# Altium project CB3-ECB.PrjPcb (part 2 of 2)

## Sheet BBoard-JX2.SchDoc: Eval Board -  BBoard JX1 connector (PWM, GPIO)
size A3; ApprovedBy: Nicolas Cherix; Author: O. Guinnard; Organization: imperix Ltd; Address1: Rue de l'Industrie 10; Address2: 1950 Sion; Address3: Switzerland; Address4: +41 27 552 06 60; Revision: C1; SheetNumber: 5; SheetTotal: 6
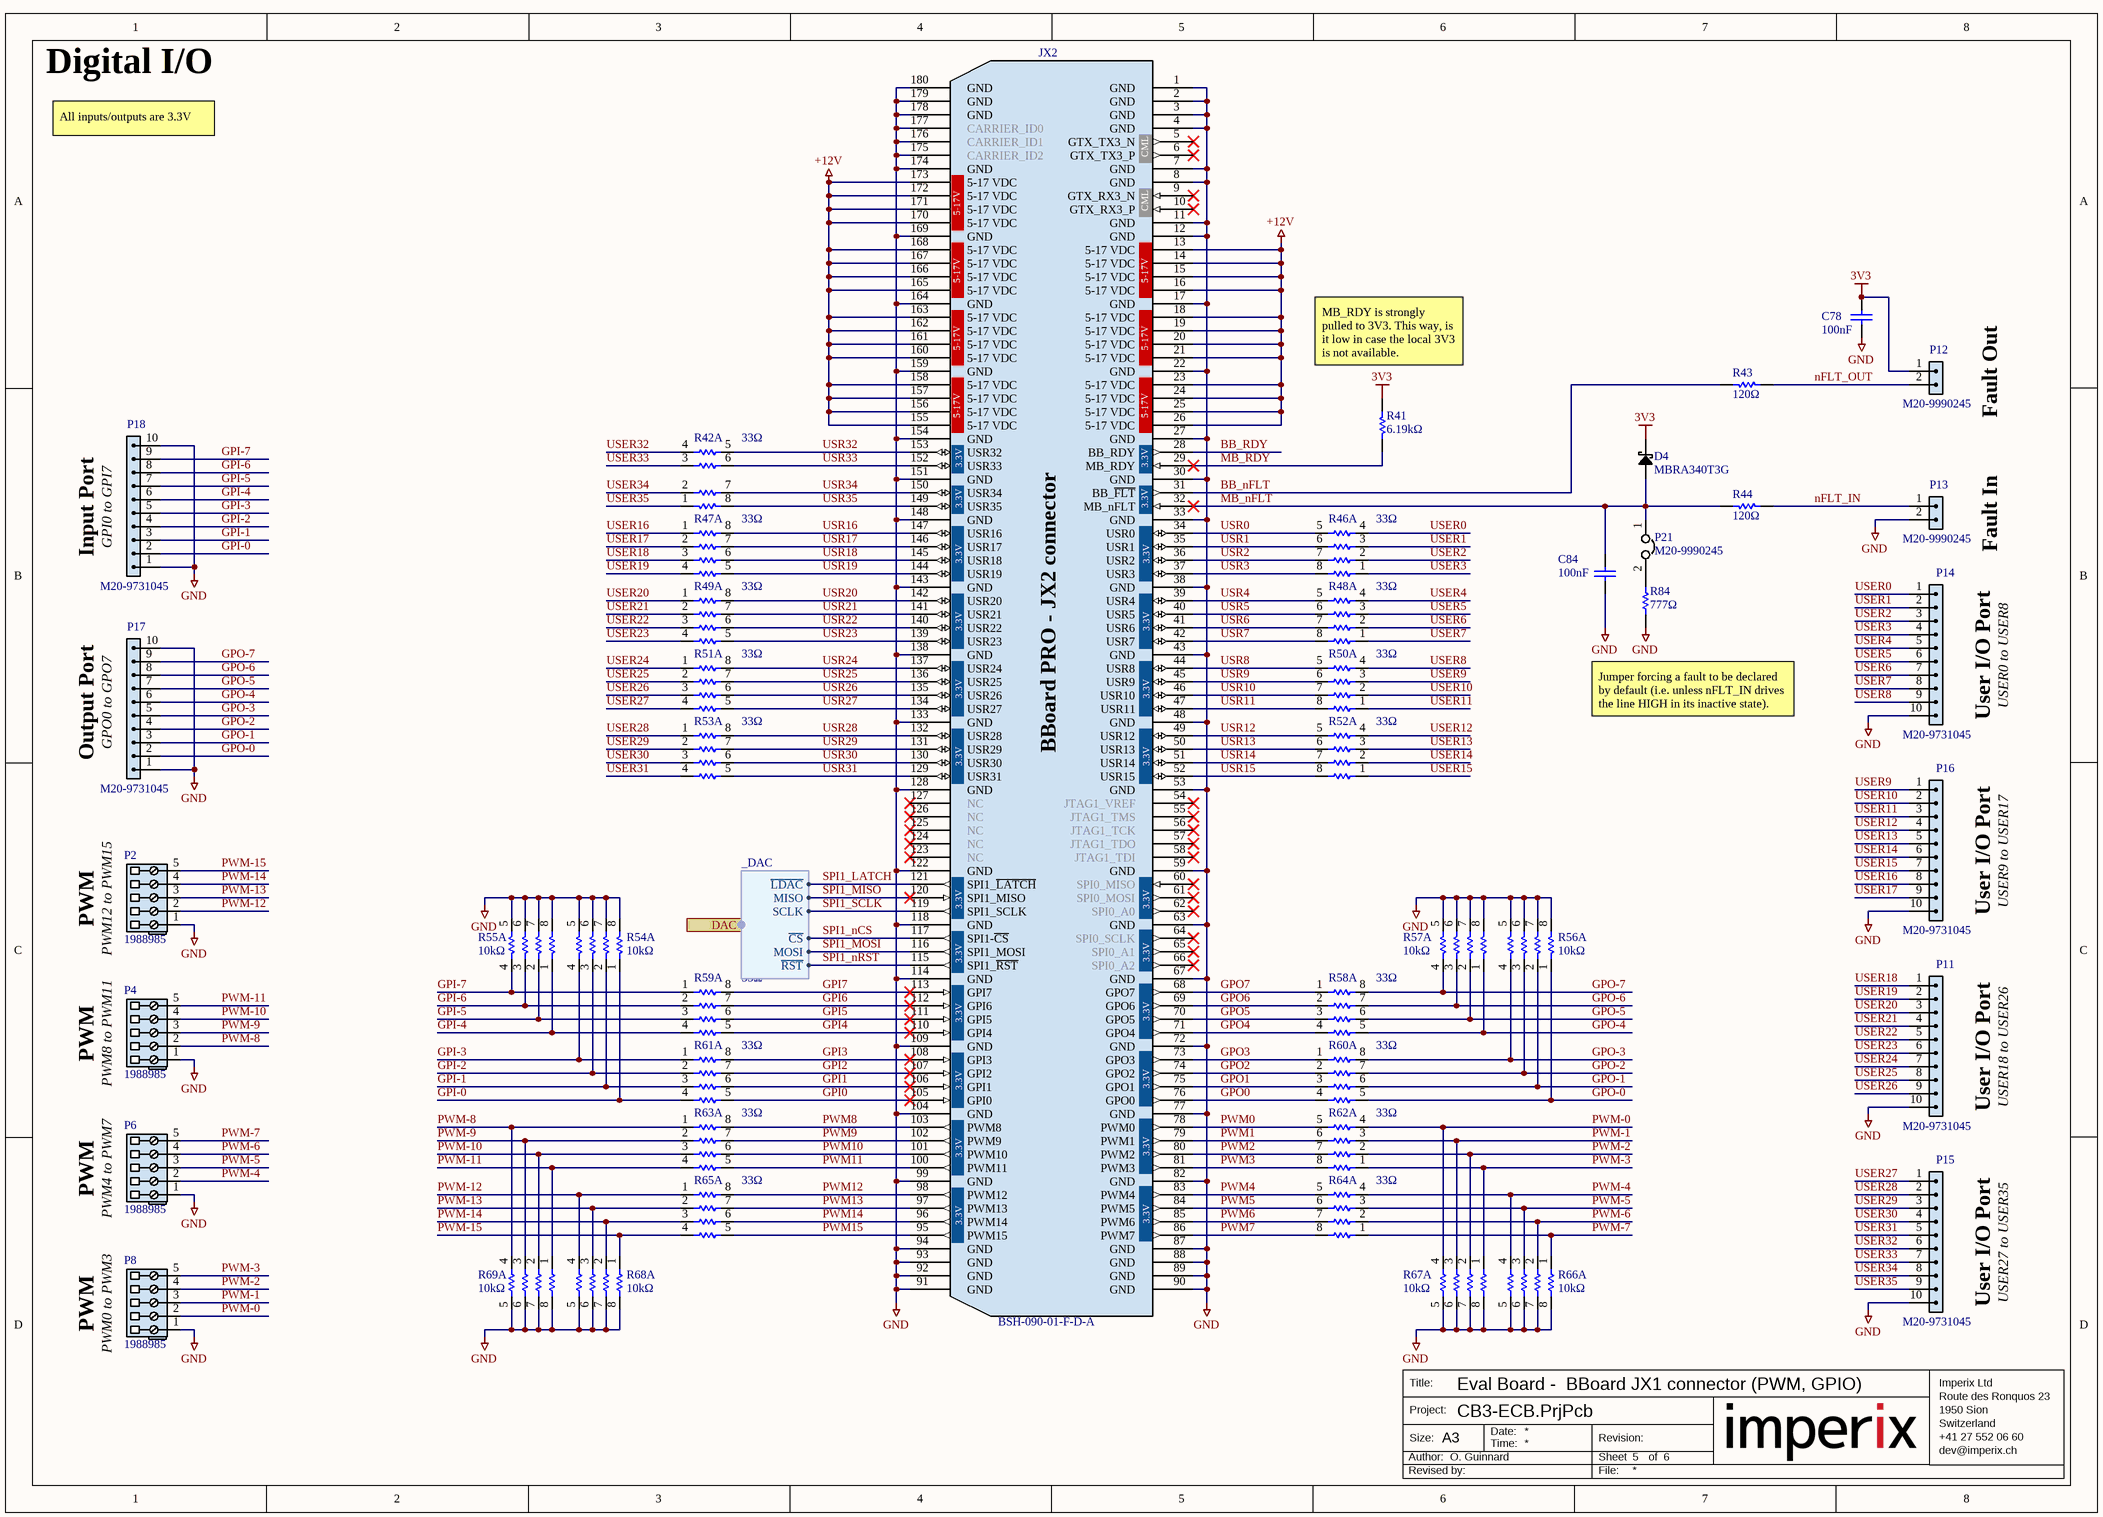
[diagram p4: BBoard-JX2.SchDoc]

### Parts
C78  value 100nF  [CAPC1005L(0402)]  (hidden comment: CAP-100NF-25V-X7R-0402-10%)
C84  value 100nF  [CAPC1005L(0402)]  (hidden comment: CAP-100NF-25V-X7R-0402-10%)
D4  MBRA340T3G  [DO-214AC]
JX2  BSH-090-01-F-D-A  [BSH-090-01-F-D-A]
P2  1988985  [1988985]
P4  1988985  [1988985]
P6  1988985  [1988985]
P8  1988985  [1988985]
P11  M20-9731045  [M20-9731045]
P12  M20-9990245  [M20-9990245]
P13  M20-9990245  [M20-9990245]
P14  M20-9731045  [M20-9731045]
P15  M20-9731045  [M20-9731045]
P16  M20-9731045  [M20-9731045]
P17  M20-9731045  [M20-9731045]
P18  M20-9731045  [M20-9731045]
P21  M20-9990245  [M20-9990245]
R41  value 6.19kΩ  [RESC1005L(0402)]  (hidden comment: RES-6.19KΩ-1/16W-100PPM-0402-1%)
R42  value 33Ω  [RESQUAD0804]  (hidden comment: EXB-28V330JX)  (parts A,B,C,D of 4)
R43  value 120Ω  [RESC1005L(0402)]  (hidden comment: RES-120Ω-1/16W-25PPM-0402-0.1%)
R44  value 120Ω  [RESC1005L(0402)]  (hidden comment: RES-120Ω-1/16W-25PPM-0402-0.1%)
R46  value 33Ω  [RESQUAD0804]  (hidden comment: EXB-28V330JX)  (parts A,B,C,D of 4)
R47  value 33Ω  [RESQUAD0804]  (hidden comment: EXB-28V330JX)  (parts A,B,C,D of 4)
R48  value 33Ω  [RESQUAD0804]  (hidden comment: EXB-28V330JX)  (parts A,B,C,D of 4)
R49  value 33Ω  [RESQUAD0804]  (hidden comment: EXB-28V330JX)  (parts A,B,C,D of 4)
R50  value 33Ω  [RESQUAD0804]  (hidden comment: EXB-28V330JX)  (parts A,B,C,D of 4)
R51  value 33Ω  [RESQUAD0804]  (hidden comment: EXB-28V330JX)  (parts A,B,C,D of 4)
R52  value 33Ω  [RESQUAD0804]  (hidden comment: EXB-28V330JX)  (parts A,B,C,D of 4)
R53  value 33Ω  [RESQUAD0804]  (hidden comment: EXB-28V330JX)  (parts A,B,C,D of 4)
R54  value 10kΩ  [RESQUAD0804]  (hidden comment: EXB-28V103JX)  (parts A,B,C,D of 4)
R55  value 10kΩ  [RESQUAD0804]  (hidden comment: EXB-28V103JX)  (parts A,B,C,D of 4)
R56  value 10kΩ  [RESQUAD0804]  (hidden comment: EXB-28V103JX)  (parts A,B,C,D of 4)
R57  value 10kΩ  [RESQUAD0804]  (hidden comment: EXB-28V103JX)  (parts A,B,C,D of 4)
R58  value 33Ω  [RESQUAD0804]  (hidden comment: EXB-28V330JX)  (parts A,B,C,D of 4)
R59  value 33Ω  [RESQUAD0804]  (hidden comment: EXB-28V330JX)  (parts A,B,C,D of 4)
R60  value 33Ω  [RESQUAD0804]  (hidden comment: EXB-28V330JX)  (parts A,B,C,D of 4)
R61  value 33Ω  [RESQUAD0804]  (hidden comment: EXB-28V330JX)  (parts A,B,C,D of 4)
R62  value 33Ω  [RESQUAD0804]  (hidden comment: EXB-28V330JX)  (parts A,B,C,D of 4)
R63  value 33Ω  [RESQUAD0804]  (hidden comment: EXB-28V330JX)  (parts A,B,C,D of 4)
R64  value 33Ω  [RESQUAD0804]  (hidden comment: EXB-28V330JX)  (parts A,B,C,D of 4)
R65  value 33Ω  [RESQUAD0804]  (hidden comment: EXB-28V330JX)  (parts A,B,C,D of 4)
R66  value 10kΩ  [RESQUAD0804]  (hidden comment: EXB-28V103JX)  (parts A,B,C,D of 4)
R67  value 10kΩ  [RESQUAD0804]  (hidden comment: EXB-28V103JX)  (parts A,B,C,D of 4)
R68  value 10kΩ  [RESQUAD0804]  (hidden comment: EXB-28V103JX)  (parts A,B,C,D of 4)
R69  value 10kΩ  [RESQUAD0804]  (hidden comment: EXB-28V103JX)  (parts A,B,C,D of 4)
R84  value 777Ω  [RESC1005L(0402)]  (hidden comment: RES-777Ω-1/16W-25PPM-0402-0.1%)

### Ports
DAC (harness _DAC)

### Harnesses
_DAC: MOSI, MISO, SCLK, ~{CS}, ~{LDAC}, ~{RST}

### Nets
3V3: C78.2 D4.K P12.1 R41.1
+12V: JX2.13(5-17_VDC) JX2.14(5-17_VDC) JX2.15(5-17_VDC) JX2.16(5-17_VDC) JX2.18(5-17_VDC) JX2.19(5-17_VDC) JX2.20(5-17_VDC) JX2.21(5-17_VDC) JX2.23(5-17_VDC) JX2.24(5-17_VDC) JX2.25(5-17_VDC) JX2.26(5-17_VDC) JX2.155(5-17_VDC) JX2.156(5-17_VDC) JX2.157(5-17_VDC) JX2.158(5-17_VDC) JX2.160(5-17_VDC) JX2.161(5-17_VDC) JX2.162(5-17_VDC) JX2.163(5-17_VDC) JX2.165(5-17_VDC) JX2.166(5-17_VDC) JX2.167(5-17_VDC) JX2.168(5-17_VDC) JX2.170(5-17_VDC) JX2.171(5-17_VDC) JX2.172(5-17_VDC) JX2.173(5-17_VDC)
GND: C78.1 C84.1 JX2.1(GND) JX2.2(GND) JX2.3(GND) JX2.4(GND) JX2.7(GND) JX2.8(GND) JX2.11(GND) JX2.12(GND) JX2.17(GND) JX2.22(GND) JX2.27(GND) JX2.30(GND) JX2.33(GND) JX2.38(GND) JX2.43(GND) JX2.48(GND) JX2.53(GND) JX2.59(GND) JX2.63(GND) JX2.67(GND) JX2.72(GND) JX2.77(GND) JX2.82(GND) JX2.87(GND) JX2.88(GND) JX2.89(GND) JX2.90(GND) JX2.91(GND) JX2.92(GND) JX2.93(GND) JX2.94(GND) JX2.99(GND) JX2.104(GND) JX2.109(GND) JX2.114(GND) JX2.118(GND) JX2.122(GND) JX2.128(GND) JX2.133(GND) JX2.138(GND) JX2.143(GND) JX2.148(GND) JX2.151(GND) JX2.154(GND) JX2.159(GND) JX2.164(GND) JX2.169(GND) JX2.174(GND) JX2.175(CARRIER_ID2) JX2.176(CARRIER_ID1) JX2.177(CARRIER_ID0) JX2.178(GND) JX2.179(GND) JX2.180(GND) P2.1 P4.1 P6.1 P8.1 P11.10 P13.2 P14.10 P15.10 P16.10 P17.1 P17.10 P18.1 P18.10 R54.5 R54.6 R54.7 R54.8 R55.5 R55.6 R55.7 R55.8 R56.5 R56.6 R56.7 R56.8 R57.5 R57.6 R57.7 R57.8 R66.5 R66.6 R66.7 R66.8 R67.5 R67.6 R67.7 R67.8 R68.5 R68.6 R68.7 R68.8 R69.5 R69.6 R69.7 R69.8 R84.1
BB_nFLT: JX2.31(BB_~{FLT}) R43.1
BB_RDY: JX2.28(BB_RDY)
GPI0: JX2.105(GPI0) R61.5
GPI1: JX2.106(GPI1) R61.6
GPI2: JX2.107(GPI2) R61.7
GPI3: JX2.108(GPI3) R61.8
GPI4: JX2.110(GPI4) R59.5
GPI5: JX2.111(GPI5) R59.6
GPI6: JX2.112(GPI6) R59.7
GPI7: JX2.113(GPI7) R59.8
GPI-0: P18.2 R54.1 R61.4
GPI-1: P18.3 R54.2 R61.3
GPI-2: P18.4 R54.3 R61.2
GPI-3: P18.5 R54.4 R61.1
GPI-4: P18.6 R55.1 R59.4
GPI-5: P18.7 R55.2 R59.3
GPI-6: P18.8 R55.3 R59.2
GPI-7: P18.9 R55.4 R59.1
GPO0: JX2.76(GPO0) R60.4
GPO1: JX2.75(GPO1) R60.3
GPO2: JX2.74(GPO2) R60.2
GPO3: JX2.73(GPO3) R60.1
GPO4: JX2.71(GPO4) R58.4
GPO5: JX2.70(GPO5) R58.3
GPO6: JX2.69(GPO6) R58.2
GPO7: JX2.68(GPO7) R58.1
GPO-0: P17.2 R56.1 R60.5
GPO-1: P17.3 R56.2 R60.6
GPO-2: P17.4 R56.3 R60.7
GPO-3: P17.5 R56.4 R60.8
GPO-4: P17.6 R57.1 R58.5
GPO-5: P17.7 R57.2 R58.6
GPO-6: P17.8 R57.3 R58.7
GPO-7: P17.9 R57.4 R58.8
MB_nFLT: C84.2 D4.A JX2.32(MB_nFLT) P21.1 R44.1
MB_RDY: JX2.29(MB_RDY) R41.2
nFLT_IN: P13.1 R44.2
nFLT_OUT: P12.2 R43.2
PWM0: JX2.78(PWM0) R62.5
PWM1: JX2.79(PWM1) R62.6
PWM2: JX2.80(PWM2) R62.7
PWM3: JX2.81(PWM3) R62.8
PWM4: JX2.83(PWM4) R64.5
PWM5: JX2.84(PWM5) R64.6
PWM6: JX2.85(PWM6) R64.7
PWM7: JX2.86(PWM7) R64.8
PWM8: JX2.103(PWM8) R63.8
PWM9: JX2.102(PWM9) R63.7
PWM10: JX2.101(PWM10) R63.6
PWM11: JX2.100(PWM11) R63.5
PWM12: JX2.98(PWM12) R65.8
PWM13: JX2.97(PWM13) R65.7
PWM14: JX2.96(PWM14) R65.6
PWM15: JX2.95(PWM15) R65.5
PWM-0: P8.2 R62.4 R67.4
PWM-1: P8.3 R62.3 R67.3
PWM-2: P8.4 R62.2 R67.2
PWM-3: P8.5 R62.1 R67.1
PWM-4: P6.2 R64.4 R66.4
PWM-5: P6.3 R64.3 R66.3
PWM-6: P6.4 R64.2 R66.2
PWM-7: P6.5 R64.1 R66.1
PWM-8: P4.2 R63.1 R69.4
PWM-9: P4.3 R63.2 R69.3
PWM-10: P4.4 R63.3 R69.2
PWM-11: P4.5 R63.4 R69.1
PWM-12: P2.2 R65.1 R68.4
PWM-13: P2.3 R65.2 R68.3
PWM-14: P2.4 R65.3 R68.2
PWM-15: P2.5 R65.4 R68.1
SPI1_LATCH: JX2.121(SPI1_~{LATCH}) ; port DAC.~{LDAC}
SPI1_MISO: JX2.120(SPI1_MISO) ; port DAC.MISO
SPI1_MOSI: JX2.116(SPI1_MOSI) ; port DAC.MOSI
SPI1_nCS: JX2.117(SPI1-~{CS}) ; port DAC.~{CS}
SPI1_nRST: JX2.115(SPI1_~{RST}) ; port DAC.~{RST}
SPI1_SCLK: JX2.119(SPI1_SCLK) ; port DAC.SCLK
USER0: P14.1 R46.4
USER1: P14.2 R46.3
USER2: P14.3 R46.2
USER3: P14.4 R46.1
USER4: P14.5 R48.4
USER5: P14.6 R48.3
USER6: P14.7 R48.2
USER7: P14.8 R48.1
USER8: P14.9 R50.4
USER9: P16.1 R50.3
USER10: P16.2 R50.2
USER11: P16.3 R50.1
USER12: P16.4 R52.4
USER13: P16.5 R52.3
USER14: P16.6 R52.2
USER15: P16.7 R52.1
USER16: P16.8 R47.1
USER17: P16.9 R47.2
USER18: P11.1 R47.3
USER19: P11.2 R47.4
USER20: P11.3 R49.1
USER21: P11.4 R49.2
USER22: P11.5 R49.3
USER23: P11.6 R49.4
USER24: P11.7 R51.1
USER25: P11.8 R51.2
USER26: P11.9 R51.3
USER27: P15.1 R51.4
USER28: P15.2 R53.1
USER29: P15.3 R53.2
USER30: P15.4 R53.3
USER31: P15.5 R53.4
USER32: P15.6 R42.4
USER33: P15.7 R42.3
USER34: P15.8 R42.2
USER35: P15.9 R42.1
USR0: JX2.34(USR0) R46.5
USR1: JX2.35(USR1) R46.6
USR2: JX2.36(USR2) R46.7
USR3: JX2.37(USR3) R46.8
USR4: JX2.39(USR4) R48.5
USR5: JX2.40(USR5) R48.6
USR6: JX2.41(USR6) R48.7
USR7: JX2.42(USR7) R48.8
USR8: JX2.44(USR8) R50.5
USR9: JX2.45(USR9) R50.6
USR10: JX2.46(USR10) R50.7
USR11: JX2.47(USR11) R50.8
USR12: JX2.49(USR12) R52.5
USR13: JX2.50(USR13) R52.6
USR14: JX2.51(USR14) R52.7
USR15: JX2.52(USR15) R52.8
USR16: JX2.147(USR16) R47.8
USR17: JX2.146(USR17) R47.7
USR18: JX2.145(USR18) R47.6
USR19: JX2.144(USR19) R47.5
USR20: JX2.142(USR20) R49.8
USR21: JX2.141(USR21) R49.7
USR22: JX2.140(USR22) R49.6
USR23: JX2.139(USR23) R49.5
USR24: JX2.137(USR24) R51.8
USR25: JX2.136(USR25) R51.7
USR26: JX2.135(USR26) R51.6
USR27: JX2.134(USR27) R51.5
USR28: JX2.132(USR28) R53.8
USR29: JX2.131(USR29) R53.7
USR30: JX2.130(USR30) R53.6
USR31: JX2.129(USR31) R53.5
USR32: JX2.153(USR32) R42.5
USR33: JX2.152(USR33) R42.6
USR34: JX2.150(USR34) R42.7
USR35: JX2.149(USR35) R42.8
NetP21_2: P21.2 R84.2

Not connected (* = marked no-connect by the designer): JX2 5(GTX_TX3_N)* 6(GTX_TX3_P)* 9(GTX_RX3_N)* 10(GTX_RX3_P)* 54(JTAG1_VREF)* 55(JTAG1_TMS)* 56(JTAG1_TCK)* 57(JTAG1_TDO)* 58(JTAG1_TDI)* 60(SPI0_MISO)* 61(SPI0_MOSI)* 62(SPI0_A0)* 64(SPI0_SCLK)* 65(SPI0_A1)* 66(SPI0_A2)* 123(NC)* 124(NC)* 125(NC)* 126(NC)* 127(NC)*

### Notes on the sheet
- Digital I/O
- All inputs/outputs are 3.3V
- (near R41) MB_RDY is strongly pulled to 3V3. This way, is it low in case the local 3V3 is not available.
- (near P12) Fault Out
- (near P18) Input Port
- (near P18) GPI0 to GPI7
- Fault In
- (near P14) User I/O Port
- USER0 to USER8
- (near P17) Output Port
- (near P17) GPO0 to GPO7
- (near R84) Jumper forcing a fault to be declared by default (i.e. unless nFLT_IN drives the line HIGH in its inactive state).
- (near P16) User I/O Port
- USER9 to USER17
- PWM
- PWM12 to PWM15
- PWM8 to PWM11
- (near P11) User I/O Port
- USER18 to USER26
- (near P6) PWM4 to PWM7
- (near P15) User I/O Port
- USER27 to USER35
- (near P8) PWM0 to PWM3

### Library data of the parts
C78 C84 = CMP-004-000006-18: CAP CER 100NF 25V X7R 0402 10% (Generic Imperix Component)
D4 = CMP-005-000028-6: Diode Schottky 40 V 3A Surface Mount SMA; Max Forward Surge Current (Ifsm): 100A; Max Repetitive Reverse Voltage (Vrrm): 40V; Polarity: Standard; Element Configuration: Single; Forward Voltage: 450mV; Max Reverse Current: 300uA
JX2 = CMP-070-000034-11: JX2 for BBoard; Max Current Rating: 1.25A; Number of Positions: 180; Max Voltage Rating (AC): 125V; Gender: Female; Mated Stacking Heights: 5mm; Pitch: 0.5mm
P2 P4 P6 P8 = CMP-003-000046-13: Conn PC Terminal Block 5 POS 3.5mm Solder Thru-Hole 17.5A; Number of Poles: 5; Voltage: 300V; Current: 10A; Approvals: UL,EAC; Number of Levels: 1; Wire Gauge (Max): 26AWG; Gender: Male; Wire Gauge (Min): 16AWG; Voltage Rating: 160V
P11 P14-P18 = CMP-003-000044-17: Connector Header Through Hole 10 position 0.100" (2.54mm); Mated Stacking Heights: 16.54mm; Current Rating: 3A; Number of Positions: 10; Voltage Rating: 750V; Gender: Male
P12 P13 = CMP-003-000045-14: Connector Header Through Hole 2 position 0.100" (2.54mm); Working Voltage: 750V; Gender: Male; Number of Positions: 2; Insulation Resistance: 10GR; Contact Resistance: 25mR; Mated Stacking Heights: 16.54mm; Current Rating: 3A; Mating Cycles: 300; Voltage: 50V
P21 = CMP-070-000025-6: Connector Header Through Hole 2 position 0.100" (2.54mm); Max Current Rating: 3A; Voltage Rating (AC): 750V; Number of Contacts: 2; Contact Resistance: 25mR; Gender: Male; Insulation Resistance: 10GR; Mating Cycles: 300; Mated Stacking Heights: 16.54mm; Voltage: 50V
R41 = CMP-009-000034-6: RES SMD 6.19KΩ 1/16W 100PPM 0402 1% (Generic Imperix Component); Temperature Coefficient: 100ppm/°C
R42 R46-R53 R58-R65 = CMP-009-000035-3: Res Thick Film Array 33 Ohm 5% ±200ppm/°C ISOL 8-Pin 0804(4 X 0402) Convex SMD Automotive T/R; Power Rating: 62.5mW; Voltage Rating (DC): 100V; Circuit Type: Isolated; Power Dissipation: 63mW; Number of Elements: 4; Number of Contacts: 8; Voltage Rating: 50V
R43 R44 = CMP-017-000008-4: RES SMD 120Ω 1/16W 25PPM 0402 0.1% (Generic Imperix Component); Temperature Coefficient: 25ppm/°C
R54-R57 R66-R69 = CMP-062-000000-4: Res Thick Film Array 10KΩ 5% ±200ppm/°C ISOL 8-Pin 0804(4 X 0402) Convex SMD Automotive T/R; Circuit Type: Isolated; Number of Contacts: 8; Number of Elements: 4; Power Dissipation: 63mW; Power Per Element: 62.5mW; Voltage Rating (DC): 100V; Voltage Rating: 50V
R84 = CMP-150-000004-2: RES SMD 777Ω 1/16W 25PPM 0402 0.1% (Generic Imperix Component); Temperature Coefficient: 25ppm/°C

## Sheet Test points.SchDoc: Eval Board -  Test points
size A3; ApprovedBy: Nicolas Cherix; Author: O. Guinnard; Organization: imperix Ltd; Address1: Rue de l'Industrie 10; Address2: 1950 Sion; Address3: Switzerland; Address4: +41 27 552 06 60; Revision: C1; SheetNumber: 6; SheetTotal: 6
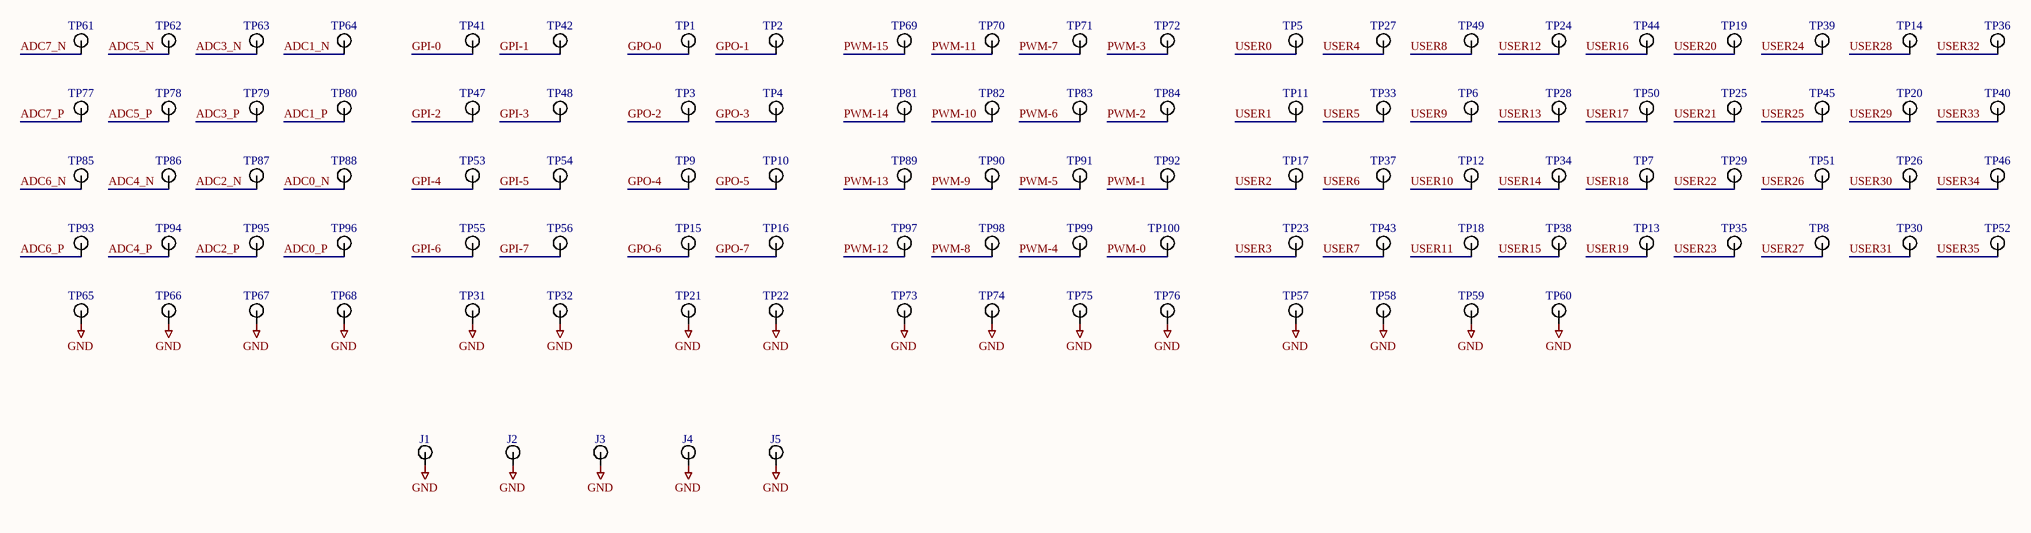
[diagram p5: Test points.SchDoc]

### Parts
J1  1625854-1  [TP-3216L(1206)]  (value not drawn)
J2  1625854-1  [TP-3216L(1206)]  (value not drawn)
J3  1625854-1  [TP-3216L(1206)]  (value not drawn)
J4  1625854-1  [TP-3216L(1206)]  (value not drawn)
J5  1625854-1  [TP-3216L(1206)]  (value not drawn)
TP1  5001  [5001]  (value not drawn)
TP2  5001  [5001]  (value not drawn)
TP3  5001  [5001]  (value not drawn)
TP4  5001  [5001]  (value not drawn)
TP5  5001  [5001]  (value not drawn)
TP6  5001  [5001]  (value not drawn)
TP7  5001  [5001]  (value not drawn)
TP8  5001  [5001]  (value not drawn)
TP9  5001  [5001]  (value not drawn)
TP10  5001  [5001]  (value not drawn)
TP11  5001  [5001]  (value not drawn)
TP12  5001  [5001]  (value not drawn)
TP13  5001  [5001]  (value not drawn)
TP14  5001  [5001]  (value not drawn)
TP15  5001  [5001]  (value not drawn)
TP16  5001  [5001]  (value not drawn)
TP17  5001  [5001]  (value not drawn)
TP18  5001  [5001]  (value not drawn)
TP19  5001  [5001]  (value not drawn)
TP20  5001  [5001]  (value not drawn)
TP21  5001  [5001]  (value not drawn)
TP22  5001  [5001]  (value not drawn)
TP23  5001  [5001]  (value not drawn)
TP24  5001  [5001]  (value not drawn)
TP25  5001  [5001]  (value not drawn)
TP26  5001  [5001]  (value not drawn)
TP27  5001  [5001]  (value not drawn)
TP28  5001  [5001]  (value not drawn)
TP29  5001  [5001]  (value not drawn)
TP30  5001  [5001]  (value not drawn)
TP31  5001  [5001]  (value not drawn)
TP32  5001  [5001]  (value not drawn)
TP33  5001  [5001]  (value not drawn)
TP34  5001  [5001]  (value not drawn)
TP35  5001  [5001]  (value not drawn)
TP36  5001  [5001]  (value not drawn)
TP37  5001  [5001]  (value not drawn)
TP38  5001  [5001]  (value not drawn)
TP39  5001  [5001]  (value not drawn)
TP40  5001  [5001]  (value not drawn)
TP41  5001  [5001]  (value not drawn)
TP42  5001  [5001]  (value not drawn)
TP43  5001  [5001]  (value not drawn)
TP44  5001  [5001]  (value not drawn)
TP45  5001  [5001]  (value not drawn)
TP46  5001  [5001]  (value not drawn)
TP47  5001  [5001]  (value not drawn)
TP48  5001  [5001]  (value not drawn)
TP49  5001  [5001]  (value not drawn)
TP50  5001  [5001]  (value not drawn)
TP51  5001  [5001]  (value not drawn)
TP52  5001  [5001]  (value not drawn)
TP53  5001  [5001]  (value not drawn)
TP54  5001  [5001]  (value not drawn)
TP55  5001  [5001]  (value not drawn)
TP56  5001  [5001]  (value not drawn)
TP57  5001  [5001]  (value not drawn)
TP58  5001  [5001]  (value not drawn)
TP59  5001  [5001]  (value not drawn)
TP60  5001  [5001]  (value not drawn)
TP61  5001  [5001]  (value not drawn)
TP62  5001  [5001]  (value not drawn)
TP63  5001  [5001]  (value not drawn)
TP64  5001  [5001]  (value not drawn)
TP65  5001  [5001]  (value not drawn)
TP66  5001  [5001]  (value not drawn)
TP67  5001  [5001]  (value not drawn)
TP68  5001  [5001]  (value not drawn)
TP69  5001  [5001]  (value not drawn)
TP70  5001  [5001]  (value not drawn)
TP71  5001  [5001]  (value not drawn)
TP72  5001  [5001]  (value not drawn)
TP73  5001  [5001]  (value not drawn)
TP74  5001  [5001]  (value not drawn)
TP75  5001  [5001]  (value not drawn)
TP76  5001  [5001]  (value not drawn)
TP77  5001  [5001]  (value not drawn)
TP78  5001  [5001]  (value not drawn)
TP79  5001  [5001]  (value not drawn)
TP80  5001  [5001]  (value not drawn)
TP81  5001  [5001]  (value not drawn)
TP82  5001  [5001]  (value not drawn)
TP83  5001  [5001]  (value not drawn)
TP84  5001  [5001]  (value not drawn)
TP85  5001  [5001]  (value not drawn)
TP86  5001  [5001]  (value not drawn)
TP87  5001  [5001]  (value not drawn)
TP88  5001  [5001]  (value not drawn)
TP89  5001  [5001]  (value not drawn)
TP90  5001  [5001]  (value not drawn)
TP91  5001  [5001]  (value not drawn)
TP92  5001  [5001]  (value not drawn)
TP93  5001  [5001]  (value not drawn)
TP94  5001  [5001]  (value not drawn)
TP95  5001  [5001]  (value not drawn)
TP96  5001  [5001]  (value not drawn)
TP97  5001  [5001]  (value not drawn)
TP98  5001  [5001]  (value not drawn)
TP99  5001  [5001]  (value not drawn)
TP100  5001  [5001]  (value not drawn)

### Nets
GND: J1.1(TP) J2.1(TP) J3.1(TP) J4.1(TP) J5.1(TP) TP21.1(TP) TP22.1(TP) TP31.1(TP) TP32.1(TP) TP57.1(TP) TP58.1(TP) TP59.1(TP) TP60.1(TP) TP65.1(TP) TP66.1(TP) TP67.1(TP) TP68.1(TP) TP73.1(TP) TP74.1(TP) TP75.1(TP) TP76.1(TP)
ADC0_N: TP88.1(TP)
ADC0_P: TP96.1(TP)
ADC1_N: TP64.1(TP)
ADC1_P: TP80.1(TP)
ADC2_N: TP87.1(TP)
ADC2_P: TP95.1(TP)
ADC3_N: TP63.1(TP)
ADC3_P: TP79.1(TP)
ADC4_N: TP86.1(TP)
ADC4_P: TP94.1(TP)
ADC5_N: TP62.1(TP)
ADC5_P: TP78.1(TP)
ADC6_N: TP85.1(TP)
ADC6_P: TP93.1(TP)
ADC7_N: TP61.1(TP)
ADC7_P: TP77.1(TP)
GPI-0: TP41.1(TP)
GPI-1: TP42.1(TP)
GPI-2: TP47.1(TP)
GPI-3: TP48.1(TP)
GPI-4: TP53.1(TP)
GPI-5: TP54.1(TP)
GPI-6: TP55.1(TP)
GPI-7: TP56.1(TP)
GPO-0: TP1.1(TP)
GPO-1: TP2.1(TP)
GPO-2: TP3.1(TP)
GPO-3: TP4.1(TP)
GPO-4: TP9.1(TP)
GPO-5: TP10.1(TP)
GPO-6: TP15.1(TP)
GPO-7: TP16.1(TP)
PWM-0: TP100.1(TP)
PWM-1: TP92.1(TP)
PWM-2: TP84.1(TP)
PWM-3: TP72.1(TP)
PWM-4: TP99.1(TP)
PWM-5: TP91.1(TP)
PWM-6: TP83.1(TP)
PWM-7: TP71.1(TP)
PWM-8: TP98.1(TP)
PWM-9: TP90.1(TP)
PWM-10: TP82.1(TP)
PWM-11: TP70.1(TP)
PWM-12: TP97.1(TP)
PWM-13: TP89.1(TP)
PWM-14: TP81.1(TP)
PWM-15: TP69.1(TP)
USER0: TP5.1(TP)
USER1: TP11.1(TP)
USER2: TP17.1(TP)
USER3: TP23.1(TP)
USER4: TP27.1(TP)
USER5: TP33.1(TP)
USER6: TP37.1(TP)
USER7: TP43.1(TP)
USER8: TP49.1(TP)
USER9: TP6.1(TP)
USER10: TP12.1(TP)
USER11: TP18.1(TP)
USER12: TP24.1(TP)
USER13: TP28.1(TP)
USER14: TP34.1(TP)
USER15: TP38.1(TP)
USER16: TP44.1(TP)
USER17: TP50.1(TP)
USER18: TP7.1(TP)
USER19: TP13.1(TP)
USER20: TP19.1(TP)
USER21: TP25.1(TP)
USER22: TP29.1(TP)
USER23: TP35.1(TP)
USER24: TP39.1(TP)
USER25: TP45.1(TP)
USER26: TP51.1(TP)
USER27: TP8.1(TP)
USER28: TP14.1(TP)
USER29: TP20.1(TP)
USER30: TP26.1(TP)
USER31: TP30.1(TP)
USER32: TP36.1(TP)
USER33: TP40.1(TP)
USER34: TP46.1(TP)
USER35: TP52.1(TP)

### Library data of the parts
J1-J5 = CMP-018-000000-12: Natural PC Test Point Plating Surface Mount Mounting Type
TP1-TP100 = CMP-049-000000-14: Black PC Test Point, Miniature Phosphor Bronze Silver Plating Through Hole Mounting Type; Hole Diameter: 1.6mm; Inside Diameter: 1.27mm; Outside Diameter: 2.54mm; Number of Contacts: 1; Insulation: Insulated

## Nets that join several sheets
3V3: Power (8 pins), DAC (5 pins), BBoard-JX1 (6 pins), BBoard-JX2 (C78.2 D4.K P12.1 R41.1)
5V2: Power (6 pins), DAC (6 pins), ADC (47 pins)
+12V: Power (13 pins), BBoard-JX2 (28 pins)
-5V: Power (C65.1 L3.2 TP125.1), DAC (C3.1 C4.1 U1.11)
GND: Power (32 pins), DAC (19 pins), ADC (77 pins), BBoard-JX1 (66 pins), BBoard-JX2 (102 pins), Test points (21 pins)
2V5REFOUT: DAC (5 pins), ADC (R81.1)
ADC0_N: ADC (P7.2 R24.3 R76.2), Test points (TP88.1)
ADC0_P: ADC (P7.3 R24.2 R77.2), Test points (TP96.1)
ADC1_N: ADC (P7.4 R26.3 R72.2), Test points (TP64.1)
ADC1_P: ADC (P7.5 R26.2 R73.2), Test points (TP80.1)
ADC2_N: ADC (P5.2 R28.3 R38.2), Test points (TP87.1)
ADC2_P: ADC (P5.3 R28.2 R39.2), Test points (TP95.1)
ADC3_N: ADC (P5.4 R3.2 R30.3), Test points (TP63.1)
ADC3_P: ADC (P5.5 R4.2 R30.2), Test points (TP79.1)
ADC4_N: ADC (P3.2 R25.3 R78.2), Test points (TP86.1)
ADC4_P: ADC (P3.3 R25.2 R79.2), Test points (TP94.1)
ADC5_N: ADC (P3.4 R27.3 R74.2), Test points (TP62.1)
ADC5_P: ADC (P3.5 R27.2 R75.2), Test points (TP78.1)
ADC6_N: ADC (P1.2 R29.3 R40.2), Test points (TP85.1)
ADC6_P: ADC (P1.3 R29.2 R71.2), Test points (TP93.1)
ADC7_N: ADC (P1.4 R31.3 R35.2), Test points (TP61.1)
ADC7_P: ADC (P1.5 R31.2 R37.2), Test points (TP77.1)
BB_RDY: Power (U12.3), BBoard-JX2 (JX2.28)
GPI-0: BBoard-JX2 (P18.2 R54.1 R61.4), Test points (TP41.1)
GPI-1: BBoard-JX2 (P18.3 R54.2 R61.3), Test points (TP42.1)
GPI-2: BBoard-JX2 (P18.4 R54.3 R61.2), Test points (TP47.1)
GPI-3: BBoard-JX2 (P18.5 R54.4 R61.1), Test points (TP48.1)
GPI-4: BBoard-JX2 (P18.6 R55.1 R59.4), Test points (TP53.1)
GPI-5: BBoard-JX2 (P18.7 R55.2 R59.3), Test points (TP54.1)
GPI-6: BBoard-JX2 (P18.8 R55.3 R59.2), Test points (TP55.1)
GPI-7: BBoard-JX2 (P18.9 R55.4 R59.1), Test points (TP56.1)
GPO-0: BBoard-JX2 (P17.2 R56.1 R60.5), Test points (TP1.1)
GPO-1: BBoard-JX2 (P17.3 R56.2 R60.6), Test points (TP2.1)
GPO-2: BBoard-JX2 (P17.4 R56.3 R60.7), Test points (TP3.1)
GPO-3: BBoard-JX2 (P17.5 R56.4 R60.8), Test points (TP4.1)
GPO-4: BBoard-JX2 (P17.6 R57.1 R58.5), Test points (TP9.1)
GPO-5: BBoard-JX2 (P17.7 R57.2 R58.6), Test points (TP10.1)
GPO-6: BBoard-JX2 (P17.8 R57.3 R58.7), Test points (TP15.1)
GPO-7: BBoard-JX2 (P17.9 R57.4 R58.8), Test points (TP16.1)
PWM-0: BBoard-JX2 (P8.2 R62.4 R67.4), Test points (TP100.1)
PWM-1: BBoard-JX2 (P8.3 R62.3 R67.3), Test points (TP92.1)
PWM-2: BBoard-JX2 (P8.4 R62.2 R67.2), Test points (TP84.1)
PWM-3: BBoard-JX2 (P8.5 R62.1 R67.1), Test points (TP72.1)
PWM-4: BBoard-JX2 (P6.2 R64.4 R66.4), Test points (TP99.1)
PWM-5: BBoard-JX2 (P6.3 R64.3 R66.3), Test points (TP91.1)
PWM-6: BBoard-JX2 (P6.4 R64.2 R66.2), Test points (TP83.1)
PWM-7: BBoard-JX2 (P6.5 R64.1 R66.1), Test points (TP71.1)
PWM-8: BBoard-JX2 (P4.2 R63.1 R69.4), Test points (TP98.1)
PWM-9: BBoard-JX2 (P4.3 R63.2 R69.3), Test points (TP90.1)
PWM-10: BBoard-JX2 (P4.4 R63.3 R69.2), Test points (TP82.1)
PWM-11: BBoard-JX2 (P4.5 R63.4 R69.1), Test points (TP70.1)
PWM-12: BBoard-JX2 (P2.2 R65.1 R68.4), Test points (TP97.1)
PWM-13: BBoard-JX2 (P2.3 R65.2 R68.3), Test points (TP89.1)
PWM-14: BBoard-JX2 (P2.4 R65.3 R68.2), Test points (TP81.1)
PWM-15: BBoard-JX2 (P2.5 R65.4 R68.1), Test points (TP69.1)
SPI1_LATCH: DAC (R13.2), BBoard-JX2 (JX2.121)
SPI1_MISO: DAC (R13.1), BBoard-JX2 (JX2.120)
SPI1_MOSI: DAC (R15.2), BBoard-JX2 (JX2.116)
SPI1_nCS: DAC (R15.3), BBoard-JX2 (JX2.117)
SPI1_nRST: DAC (R15.1), BBoard-JX2 (JX2.115)
SPI1_SCLK: DAC (R15.4), BBoard-JX2 (JX2.119)
USER0: BBoard-JX2 (P14.1 R46.4), Test points (TP5.1)
USER1: BBoard-JX2 (P14.2 R46.3), Test points (TP11.1)
USER2: BBoard-JX2 (P14.3 R46.2), Test points (TP17.1)
USER3: BBoard-JX2 (P14.4 R46.1), Test points (TP23.1)
USER4: BBoard-JX2 (P14.5 R48.4), Test points (TP27.1)
USER5: BBoard-JX2 (P14.6 R48.3), Test points (TP33.1)
USER6: BBoard-JX2 (P14.7 R48.2), Test points (TP37.1)
USER7: BBoard-JX2 (P14.8 R48.1), Test points (TP43.1)
USER8: BBoard-JX2 (P14.9 R50.4), Test points (TP49.1)
USER9: BBoard-JX2 (P16.1 R50.3), Test points (TP6.1)
USER10: BBoard-JX2 (P16.2 R50.2), Test points (TP12.1)
USER11: BBoard-JX2 (P16.3 R50.1), Test points (TP18.1)
USER12: BBoard-JX2 (P16.4 R52.4), Test points (TP24.1)
USER13: BBoard-JX2 (P16.5 R52.3), Test points (TP28.1)
USER14: BBoard-JX2 (P16.6 R52.2), Test points (TP34.1)
USER15: BBoard-JX2 (P16.7 R52.1), Test points (TP38.1)
USER16: BBoard-JX2 (P16.8 R47.1), Test points (TP44.1)
USER17: BBoard-JX2 (P16.9 R47.2), Test points (TP50.1)
USER18: BBoard-JX2 (P11.1 R47.3), Test points (TP7.1)
USER19: BBoard-JX2 (P11.2 R47.4), Test points (TP13.1)
USER20: BBoard-JX2 (P11.3 R49.1), Test points (TP19.1)
USER21: BBoard-JX2 (P11.4 R49.2), Test points (TP25.1)
USER22: BBoard-JX2 (P11.5 R49.3), Test points (TP29.1)
USER23: BBoard-JX2 (P11.6 R49.4), Test points (TP35.1)
USER24: BBoard-JX2 (P11.7 R51.1), Test points (TP39.1)
USER25: BBoard-JX2 (P11.8 R51.2), Test points (TP45.1)
USER26: BBoard-JX2 (P11.9 R51.3), Test points (TP51.1)
USER27: BBoard-JX2 (P15.1 R51.4), Test points (TP8.1)
USER28: BBoard-JX2 (P15.2 R53.1), Test points (TP14.1)
USER29: BBoard-JX2 (P15.3 R53.2), Test points (TP20.1)
USER30: BBoard-JX2 (P15.4 R53.3), Test points (TP26.1)
USER31: BBoard-JX2 (P15.5 R53.4), Test points (TP30.1)
USER32: BBoard-JX2 (P15.6 R42.4), Test points (TP36.1)
USER33: BBoard-JX2 (P15.7 R42.3), Test points (TP40.1)
USER34: BBoard-JX2 (P15.8 R42.2), Test points (TP46.1)
USER35: BBoard-JX2 (P15.9 R42.1), Test points (TP52.1)

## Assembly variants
Standard variant: not fitted C16 C17 C17 C23 C24 C24 C26 C26 C27 C27 C34 C34 C35 C35 C36 C36 C37 C37 C44 C44 C45 C45 C48 C48 C49 C49 C54 C54 C55 C55 C? M1 M2 M3 M4 M5 M6 M7 M8 M9 M9 M10 M10 M11 M11 M12 M12 M13 M14 M15 M16 M17 M18 M18 M19 M19 M20 M20 M21 M22 M23 M24 M? R43 R44 R? R? TP1 TP1 TP2 TP2 TP3 TP3 TP4 TP4 TP5 TP5 TP6 TP6 TP7 TP7 TP8 TP8 TP9 TP9 TP10 TP10 TP11 TP11 TP12 TP12 TP13 TP13 TP14 TP14 TP15 TP15 TP16 TP16 TP17 TP17 TP18 TP18 TP19 TP19 TP20 TP20 TP21 TP21 TP22 TP22 TP23 TP23 TP24 TP24 TP25 TP25 TP26 TP26 TP27 TP27 TP28 TP28 TP29 TP29 TP30 TP30 TP31 TP31 TP32 TP32 TP33 TP33 TP34 TP34 TP35 TP35 TP36 TP36 TP37 TP37 TP38 TP38 TP39 TP39 TP40 TP40 TP41 TP41 TP42 TP42 TP43 TP43 TP44 TP44 TP45 TP45 TP46 TP46 TP47 TP47 TP48 TP48 TP49 TP49 TP50 TP50 TP51 TP51 TP52 TP52 TP53 TP53 TP54 TP54 TP55 TP55 TP56 TP56 TP57 TP57 TP58 TP58 TP59 TP59 TP60 TP60 TP61 TP61 TP62 TP62 TP63 TP63 TP64 TP64 TP65 TP65 TP66 TP66 TP67 TP67 TP68 TP68 TP69 TP69 TP70 TP70 TP71 TP71 TP72 TP72 TP73 TP73 TP74 TP74 TP75 TP75 TP76 TP76 TP77 TP77 TP78 TP78 TP79 TP79 TP80 TP80 TP81 TP81 TP82 TP82 TP83 TP83 TP84 TP84 TP85 TP85 TP86 TP86 TP87 TP87 TP88 TP88 TP89 TP89 TP90 TP90 TP91 TP91 TP92 TP92 TP93 TP93 TP94 TP94 TP95 TP95 TP96 TP96 TP97 TP97 TP98 TP98 TP99 TP99 TP100 TP100 TP101 TP101 TP102 TP103 TP103 TP104 TP104 TP105 TP106 TP107 TP107 TP108 TP109 TP109 TP110 TP110 TP111 TP111 TP112 TP112 TP113 TP113 TP114 TP114 TP115 TP115 TP116 TP116 TP117 TP117 TP118 TP118 TP119 TP119 TP120 TP120 TP121 TP121 TP122 TP123 TP124 TP125 TP126 TP127 TP128 TP129 TP130 TP131 U?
